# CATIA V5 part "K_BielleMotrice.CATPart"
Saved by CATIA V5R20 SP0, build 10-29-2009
Part number: Bielle_motrice
Bounding box of the stored display mesh (mm): x -195 to -75, y -122.303 to -107.303, z 35 to 65
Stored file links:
  G:\Khaled_CFAO_2011\ST2M\ST2M_GR2\jcoetard\Khaled\CAD_CATIA\K_BielleMotrice.CATPart
  J:\Thinkmotion\Thinkmotion_COETARD\Maquette_catia\Maquette_catia_R20_Licence_education\jcharlescoetard.CATPRODUCT\Assemblage_Pince_Prehension_Mors_Paralleles.CATProduct
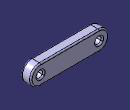
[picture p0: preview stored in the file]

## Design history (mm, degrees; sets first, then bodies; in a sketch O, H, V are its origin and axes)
Set1
  Plane1 "Plan_bielle_motrice": linked copy from another document
  Point1: linked copy from another document
  Point2: linked copy from another document
Body1 (main body)
  Sketch1 on Plane1, origin (0, -107.303, 0), H (-1, 0, 0), V (0, 0, 1)
    construction line L1 (90, 50) -> (180, 50)
    point P1 (90, 50)
    point P2 (180, 50)
    line L2 (90, 65) -> (180, 65)
    line L3 (180, 35) -> (90, 35)
    arc A1 centre (180, 50) radius 15 from (180, 65) to (180, 35) cw
    arc A2 centre (90, 50) radius 15 from (90, 35) to (90, 65) cw
    reference projected point E1 (180, 50) from Point1
    reference projected point E2 (90, 50) from Point2
    distance L2 L3 = 30
    tangency: A1 L2, A2 L2, A1 L3, A2 L3
    coincidence: P2 E1, P1 E2
  Pad1: profile Sketch1, direction (0, -1, 0), length 15
  Sketch2 on start face of Pad1, origin (-80, -107.303, 33.3333), H (1, 0, 0), V (0, 0, -1)
    point P1 (-100, -16.6667)
    reference projected point E1 (-100, -16.6667) from Point1
    coincidence: E1 P1
  Hole1: placed by Sketch2, at (-180, -107.303, 50) direction (0, -1, 0), diameter 10, depth 20
  Sketch3 on start face of Pad1, origin (-30, -107.303, 33.3333), H (1, 0, 0), V (0, 0, -1)
    point P1 (-60, -16.6667)
    reference projected point E1 (-60, -16.6667) from Point2
    coincidence: E1 P1
  Hole2: placed by Sketch3, at (-90, -107.303, 50) direction (0, -1, 0), diameter 10, depth 20
  Fillet1: radius 2, on start face of Pad1; end face of Pad1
